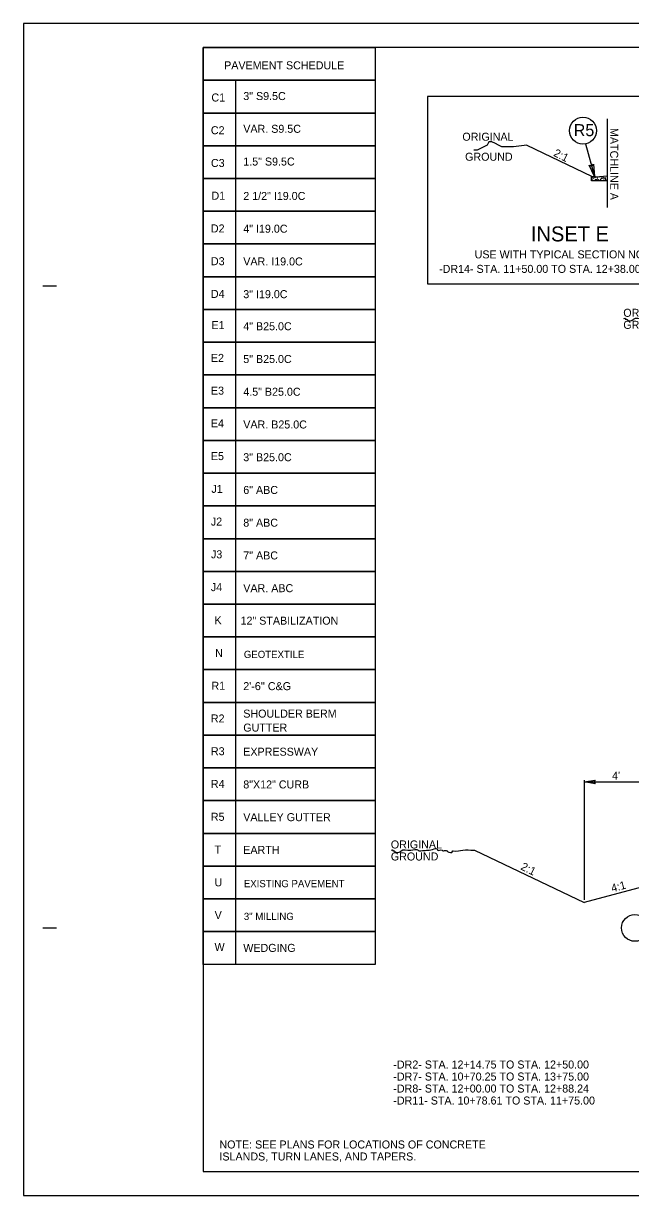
# Model space of a CAD drawing. Extents: x 18938 to 19565, y 6931 to 7973.
# Drawn here: x 19155.2 to 19231, y 6930.7 to 7077.1 of the extents above; entities that cross this region are included whole.
import ezdxf

# ---------------------------------------------------------------- set-up
doc = ezdxf.new("R2010")
doc.units = 0
for name, color, linetype in [('Default', 7, 'Continuous'), ('Old_Level_11', 7, 'Continuous'), ('Old_Level_2', 7, 'Continuous'), ('Prop Dimension', 7, 'Continuous'), ('Prop Shade Medium', 7, 'Continuous'), ('Prop Terminator CELL', 7, 'Continuous'), ('Sheet Data Field CELL', 7, 'Continuous'), ('Sheet Sticker Incomplete CELL', 7, 'Continuous'), ('Sheet Typical CELL', 7, 'Continuous'), ('Typical Curb CELL', 7, 'Continuous'), ('Typical Detail Wedge2 CELL', 7, 'Continuous'), ('Typical ID Circle CELL', 7, 'Continuous'), ('Typical Pavement Slope CELL', 7, 'Continuous'), ('Typical Pavement Slope Information CELL', 7, 'Continuous'), ('Typical Shoulder Slope Information CELL', 7, 'Continuous'), ('Typical Terminator CELL', 7, 'Continuous'), ('Typical Text General CELL', 7, 'Continuous')]:
    doc.layers.add(name, color=color, linetype=linetype)

# ---------------------------------------------------------------- blocks, each defined once
blk = doc.blocks.new('VALLEY GUTTER')
at = {"layer": 'Sheet Sticker Incomplete CELL'}
for p, q in [((0, 0), (1, -0.08)), ((0, -0.58), (0, 0)), ((2, 0), (1, -0.08)), ((2, -0.58), (2, 0)), ((2, -0.58), (0, -0.58)), ((0.17, -0.23), (0.26, -0.11)), ((0.29, -0.23), (0.17, -0.23)), ((0.26, -0.11), (0.29, -0.23)), ((0.53, -0.47), (0.59, -0.36)), ((0.69, -0.43), (0.53, -0.47)), ((0.59, -0.36), (0.69, -0.43)), ((1.22, -0.28), (1.3, -0.16)), ((1.34, -0.27), (1.22, -0.28)), ((1.3, -0.16), (1.34, -0.27)), ((1.74, -0.51), (1.82, -0.39)), ((1.86, -0.51), (1.74, -0.51)), ((1.82, -0.39), (1.86, -0.51))]:
    blk.add_line(p, q, dxfattribs=at)
for centre in [(0.06, -0.51), (0.1, -0.1), (0.12, -0.54), (0.14, -0.34), (0.15, -0.41), (0.26, -0.5), (0.43, -0.36), (0.5, -0.13), (0.72, -0.14), (0.75, -0.29), (0.81, -0.33), (0.84, -0.2), (0.87, -0.42), (1.07, -0.19), (1.12, -0.45), (1.18, -0.48), (1.21, -0.35), (1.36, -0.49), (1.47, -0.14), (1.53, -0.32), (1.59, -0.35), (1.62, -0.22), (1.68, -0.5), (1.7, -0.23), (1.75, -0.19), (1.79, -0.31), (1.91, -0.47), (1.99, -0.27)]:
    blk.add_circle(centre, 0.00802, dxfattribs=at)

msp = doc.modelspace()

# ---------------------------------------------------------------- linework, layer by layer
at = {"layer": 'Default'}
msp.add_lwpolyline([(19205.68, 7044.59), (19238.72, 7044.59), (19238.72, 7067.99), (19205.68, 7067.99)], close=True, dxfattribs=at)
at = {"layer": 'Prop Dimension'}
msp.add_lwpolyline([(19155.17, 6930.67), (19382.43, 6930.67), (19382.43, 7077.1), (19155.17, 7077.1)], close=True, dxfattribs=at)
at = {"layer": 'Prop Shade Medium'}
for p, q in [((19218.06, 7061.88), (19226.14, 7058.01)), ((19211.52, 6973.82), (19225.26, 6967.26)), ((19233.19, 6969.39), (19225.26, 6967.26))]:
    msp.add_line(p, q, dxfattribs=at)
msp.add_lwpolyline([(19218.06, 7061.88), (19216.42, 7061.67), (19216.01, 7061.67), (19215.38, 7061.67), (19214.97, 7061.67), (19214.55, 7061.88), (19214.14, 7062.09), (19213.72, 7062.3), (19213.31, 7062.3), (19213.1, 7061.88), (19212.69, 7061.67), (19212.27, 7061.46), (19211.86, 7061.26), (19211.44, 7061.26)], dxfattribs=at)
at = {"layer": 'Sheet Data Field CELL'}
msp.add_lwpolyline([(19226.61, 6982.11), (19225.26, 6982.34), (19226.61, 6982.58), (19226.44, 6982.34)], close=True, dxfattribs=at)
at = {"layer": 'Sheet Typical CELL'}
for p, q in [((19228.14, 7054.09), (19228.14, 7065.2)), ((19225.26, 6982.55), (19225.26, 6967.62)), ((19225.26, 6982.34), (19234.28, 6982.34))]:
    msp.add_line(p, q, dxfattribs=at)
at = {"layer": 'Typical Curb CELL'}
for points in [[(19230.21, 7040.24), (19230.38, 7040.24), (19230.38, 7040.16), (19230.55, 7040.16), (19230.64, 7040.07), (19231.32, 7040.07), (19231.41, 7040.16), (19232.61, 7040.24), (19233.55, 7040.24), (19233.63, 7040.16), (19233.89, 7040.16), (19235.35, 7040.33), (19235.95, 7040.33), (19235.95, 7040.24), (19236.55, 7040.24), (19236.63, 7040.16), (19236.72, 7040.16), (19237.15, 7040.16), (19237.23, 7040.07), (19237.83, 7040.07), (19237.83, 7040.16), (19237.92, 7040.16), (19239.12, 7040.24), (19240.49, 7040.24), (19240.57, 7040.24)], [(19201.16, 6973.82), (19201.33, 6973.82), (19201.33, 6973.74), (19201.5, 6973.74), (19201.59, 6973.65), (19202.27, 6973.65), (19202.36, 6973.74), (19203.56, 6973.82), (19204.5, 6973.82), (19204.58, 6973.74), (19204.84, 6973.74), (19206.3, 6973.91), (19206.9, 6973.91), (19206.9, 6973.82), (19207.5, 6973.82), (19207.58, 6973.74), (19207.67, 6973.74), (19208.1, 6973.74), (19208.18, 6973.65), (19208.78, 6973.65), (19208.78, 6973.74), (19208.87, 6973.74), (19210.07, 6973.82), (19211.44, 6973.82), (19211.52, 6973.82)]]:
    msp.add_spline(points, degree=3, dxfattribs=at)
at = {"layer": 'Typical Pavement Slope CELL'}
msp.add_lwpolyline([(19177.64, 7074.1), (19199.14, 7074.1), (19199.14, 7070), (19177.64, 7070)], close=True, dxfattribs=at)
for points in [[(19181.73, 7065.91), (19177.64, 7065.91), (19177.64, 7070), (19199.14, 7070), (19199.14, 7065.91), (19181.73, 7065.91), (19181.73, 7070)], [(19181.73, 7061.82), (19177.64, 7061.82), (19177.64, 7065.91), (19199.14, 7065.91), (19199.14, 7061.82), (19181.73, 7061.82), (19181.73, 7065.91)], [(19181.73, 7057.73), (19177.64, 7057.73), (19177.64, 7061.82), (19199.14, 7061.82), (19199.14, 7057.73), (19181.73, 7057.73), (19181.73, 7061.82)], [(19181.73, 7053.64), (19177.64, 7053.64), (19177.64, 7057.73), (19199.14, 7057.73), (19199.14, 7053.64), (19181.73, 7053.64), (19181.73, 7057.73)], [(19181.73, 7049.55), (19177.64, 7049.55), (19177.64, 7053.64), (19199.14, 7053.64), (19199.14, 7049.55), (19181.73, 7049.55), (19181.73, 7053.64)], [(19181.73, 7045.46), (19177.64, 7045.46), (19177.64, 7049.55), (19199.14, 7049.55), (19199.14, 7045.46), (19181.73, 7045.46), (19181.73, 7049.55)], [(19181.73, 7041.37), (19177.64, 7041.37), (19177.64, 7045.46), (19199.14, 7045.46), (19199.14, 7041.37), (19181.73, 7041.37), (19181.73, 7045.46)], [(19181.73, 7037.28), (19177.64, 7037.28), (19177.64, 7041.37), (19199.14, 7041.37), (19199.14, 7037.28), (19181.73, 7037.28), (19181.73, 7041.37)], [(19181.73, 7033.19), (19177.64, 7033.19), (19177.64, 7037.28), (19199.14, 7037.28), (19199.14, 7033.19), (19181.73, 7033.19), (19181.73, 7037.28)], [(19181.73, 7029.1), (19177.64, 7029.1), (19177.64, 7033.19), (19199.14, 7033.19), (19199.14, 7029.1), (19181.73, 7029.1), (19181.73, 7033.19)], [(19181.73, 7025.01), (19177.64, 7025.01), (19177.64, 7029.1), (19199.14, 7029.1), (19199.14, 7025.01), (19181.73, 7025.01), (19181.73, 7029.1)], [(19181.73, 7020.91), (19177.64, 7020.91), (19177.64, 7025.01), (19199.14, 7025.01), (19199.14, 7020.91), (19181.73, 7020.91), (19181.73, 7025.01)], [(19181.73, 7016.82), (19177.64, 7016.82), (19177.64, 7020.91), (19199.14, 7020.91), (19199.14, 7016.82), (19181.73, 7016.82), (19181.73, 7020.91)], [(19181.73, 7012.73), (19177.64, 7012.73), (19177.64, 7016.82), (19199.14, 7016.82), (19199.14, 7012.73), (19181.73, 7012.73), (19181.73, 7016.82)], [(19181.73, 7008.64), (19177.64, 7008.64), (19177.64, 7012.73), (19199.14, 7012.73), (19199.14, 7008.64), (19181.73, 7008.64), (19181.73, 7012.73)], [(19181.73, 7004.55), (19177.64, 7004.55), (19177.64, 7008.64), (19199.14, 7008.64), (19199.14, 7004.55), (19181.73, 7004.55), (19181.73, 7008.64)], [(19181.73, 7000.46), (19177.64, 7000.46), (19177.64, 7004.55), (19199.14, 7004.55), (19199.14, 7000.46), (19181.73, 7000.46), (19181.73, 7004.55)], [(19181.73, 6996.37), (19177.64, 6996.37), (19177.64, 7000.46), (19199.14, 7000.46), (19199.14, 6996.37), (19181.73, 6996.37), (19181.73, 7000.46)], [(19181.73, 6992.28), (19177.64, 6992.28), (19177.64, 6996.37), (19199.14, 6996.37), (19199.14, 6992.28), (19181.73, 6992.28), (19181.73, 6996.37)], [(19181.73, 6988.19), (19177.64, 6988.19), (19177.64, 6992.28), (19199.14, 6992.28), (19199.14, 6988.19), (19181.73, 6988.19), (19181.73, 6992.28)], [(19181.73, 6984.1), (19177.64, 6984.1), (19177.64, 6988.19), (19199.14, 6988.19), (19199.14, 6984.1), (19181.73, 6984.1), (19181.73, 6988.19)], [(19181.73, 6980.01), (19177.64, 6980.01), (19177.64, 6984.1), (19199.14, 6984.1), (19199.14, 6980.01), (19181.73, 6980.01), (19181.73, 6984.1)], [(19181.73, 6975.92), (19177.64, 6975.92), (19177.64, 6980.01), (19199.14, 6980.01), (19199.14, 6975.92), (19181.73, 6975.92), (19181.73, 6980.01)], [(19181.73, 6971.82), (19177.64, 6971.82), (19177.64, 6975.92), (19199.14, 6975.92), (19199.14, 6971.82), (19181.73, 6971.82), (19181.73, 6975.92)], [(19181.73, 6967.73), (19177.64, 6967.73), (19177.64, 6971.82), (19199.14, 6971.82), (19199.14, 6967.73), (19181.73, 6967.73), (19181.73, 6971.82)], [(19181.73, 6963.64), (19177.64, 6963.64), (19177.64, 6967.73), (19199.14, 6967.73), (19199.14, 6963.64), (19181.73, 6963.64), (19181.73, 6967.73)], [(19181.73, 6959.55), (19177.64, 6959.55), (19177.64, 6963.64), (19199.14, 6963.64), (19199.14, 6959.55), (19181.73, 6959.55), (19181.73, 6963.64)]]:
    msp.add_lwpolyline(points, dxfattribs=at)
at = {"layer": 'Typical Pavement Slope Information CELL'}
for p, q in [((19157.59, 7044.34), (19159.28, 7044.34)), ((19157.59, 6964.1), (19159.28, 6964.1))]:
    msp.add_line(p, q, dxfattribs=at)
msp.add_lwpolyline([(19380.14, 7074.1), (19177.64, 7074.1), (19177.64, 6933.68), (19380.14, 6933.68)], close=True, dxfattribs=at)
at = {"layer": 'Typical Terminator CELL'}
msp.add_line((19225.4, 7062.06), (19226.55, 7057.97), dxfattribs=at)
for centre in [(19225.09, 7063.71), (19231.58, 6964.11)]:
    msp.add_circle(centre, 1.68, dxfattribs=at)
at = {"layer": 'Typical Text General CELL'}
msp.add_lwpolyline([(19226.39, 7059.54), (19226.55, 7057.97), (19225.86, 7059.4), (19226.18, 7059.28)], close=True, dxfattribs=at)

# ---------------------------------------------------------------- block references
at = {"layer": 'Typical ID Circle CELL'}
msp.add_blockref('VALLEY GUTTER', (19226.14, 7058.01), dxfattribs=at)

# ---------------------------------------------------------------- texts
at = {"layer": 'Old_Level_11'}
msp.add_text('INSET E', height=1.875, rotation=0, dxfattribs=at).set_placement((19218.58, 7049.87))
for s, p in [('NOTE: SEE PLANS FOR LOCATIONS OF CONCRETE', (19179.66, 6936.55)), ('ISLANDS, TURN LANES, AND TAPERS.', (19179.66, 6935.05))]:
    msp.add_text(s, height=1, dxfattribs=at).set_placement(p)
at = {"layer": 'Old_Level_2'}
for s, p in [('ORIGINAL', (19230.13, 7040.45)), ('GROUND', (19230.13, 7038.95)), ('ORIGINAL', (19201.08, 6974.03)), ('GROUND', (19201.08, 6972.53))]:
    msp.add_text(s, height=1, rotation=360, dxfattribs=at).set_placement(p)
at = {"layer": 'Prop Shade Medium'}
for s, p in [('ORIGINAL', (19210.02, 7062.45)), ('GROUND', (19210.36, 7059.95))]:
    msp.add_text(s, height=1, rotation=360, dxfattribs=at).set_placement(p)
at = {"layer": 'Prop Terminator CELL'}
msp.add_text('R5', height=1.5, rotation=0.0003, dxfattribs=at).set_placement((19223.94, 7063.02))
at = {"layer": 'Typical Detail Wedge2 CELL'}
msp.add_text('MATCHLINE A ', height=1, rotation=270, dxfattribs=at).set_placement((19228.49, 7064.04))
for s, p in [("4'", (19228.73, 6982.63)), ('-DR2- STA. 12+14.75 TO STA. 12+50.00', (19201.39, 6946.54)), ('-DR7- STA. 10+70.25 TO STA. 13+75.00', (19201.39, 6945.04)), ('-DR8- STA. 12+00.00 TO STA. 12+88.24', (19201.39, 6943.54)), ('-DR11- STA. 10+78.61 TO STA. 11+75.00', (19201.39, 6942.04))]:
    msp.add_text(s, height=1, dxfattribs=at).set_placement(p)
at = {"layer": 'Typical Pavement Slope CELL'}
for s, height, p in [('PAVEMENT SCHEDULE', 1, (19180.25, 7071.37)), ('C1', 1, (19178.66, 7067.35)), ('3" S9.5C', 1, (19182.64, 7067.53)), ('C2', 1, (19178.59, 7063.26)), ('VAR. S9.5C', 1, (19182.64, 7063.44)), ('C3', 1, (19178.6, 7059.17)), ('1.5" S9.5C', 1, (19182.64, 7059.35)), ('D1', 1, (19178.66, 7055.08)), ('2 1/2" I19.0C', 1, (19182.64, 7055.05)), ('D2', 1, (19178.59, 7050.99)), ('4" I19.0C', 1, (19182.64, 7050.96)), ('D3', 1, (19178.6, 7046.9)), ('VAR. I19.0C', 1, (19182.64, 7046.87)), ('D4', 1, (19178.59, 7042.81)), ('3" I19.0C', 1, (19182.64, 7042.78)), ('E1', 1, (19178.66, 7038.91)), ('4" B25.0C', 1, (19182.64, 7038.77)), ('E2', 1, (19178.59, 7034.82)), ('5" B25.0C', 1, (19182.64, 7034.68)), ('E3', 1, (19178.6, 7030.73)), ('4.5" B25.0C', 1, (19182.64, 7030.59)), ('E4', 1, (19178.59, 7026.64)), ('VAR. B25.0C', 1, (19182.64, 7026.5)), ('E5', 1, (19178.59, 7022.55)), ('3" B25.0C', 1, (19182.64, 7022.41)), ('J1', 1, (19178.66, 7018.46)), ('6" ABC', 1, (19182.64, 7018.32)), ('J2', 1, (19178.59, 7014.37)), ('8" ABC', 1, (19182.64, 7014.23)), ('J3', 1, (19178.6, 7010.28)), ('7" ABC', 1, (19182.64, 7010.14)), ('J4', 1, (19178.59, 7006.18)), ('VAR. ABC', 1, (19182.64, 7006.05)), ('K', 1, (19179.05, 7002.04)), ('12" STABILIZATION', 1, (19182.3, 7001.99)), ('N', 1, (19179.12, 6997.94)), ('GEOTEXTILE', 0.9, (19182.71, 6997.83)), ('R1', 1, (19178.66, 6993.86)), ("2'-6'' C&G", 1, (19182.64, 6993.81)), ('R2', 1, (19178.59, 6989.77)), ('SHOULDER BERM ', 1, (19182.64, 6990.38)), ('GUTTER', 1, (19182.64, 6988.63)), ('R3', 1, (19178.6, 6985.68)), ('EXPRESSWAY ', 1, (19182.64, 6985.62)), ('R4', 1, (19178.59, 6981.59)), ('8"X12" CURB', 1, (19182.64, 6981.53)), ('R5', 1, (19178.59, 6977.49)), ('VALLEY GUTTER', 1, (19182.64, 6977.44)), ('T', 1, (19179.05, 6973.4)), ('EARTH', 1, (19182.64, 6973.35)), ('U', 1, (19179.05, 6969.3)), ('EXISTING PAVEMENT', 0.9, (19182.71, 6969.19)), ('V', 1, (19179.06, 6965.21)), ('3" MILLING', 0.9, (19182.71, 6965.1)), ('W', 1, (19179.05, 6961.22)), ('WEDGING', 1, (19182.64, 6961.11))]:
    msp.add_text(s, height=height, dxfattribs=at).set_placement(p)
at = {"layer": 'Typical Shoulder Slope Information CELL'}
for s, rotation, p in [('2:1', 333.4349, (19221.33, 7060.59)), ('USE WITH TYPICAL SECTION NO. 17', 0, (19211.55, 7047.75)), ('-DR14- STA. 11+50.00 TO STA. 12+38.00 LT', 0, (19207.11, 7045.94)), ('2:1', 333.4349, (19217.23, 6971.45)), ('4:1', 15.1346, (19228.75, 6968.55))]:
    msp.add_text(s, height=1, rotation=rotation, dxfattribs=at).set_placement(p)

doc.saveas('drawing.dxf')
